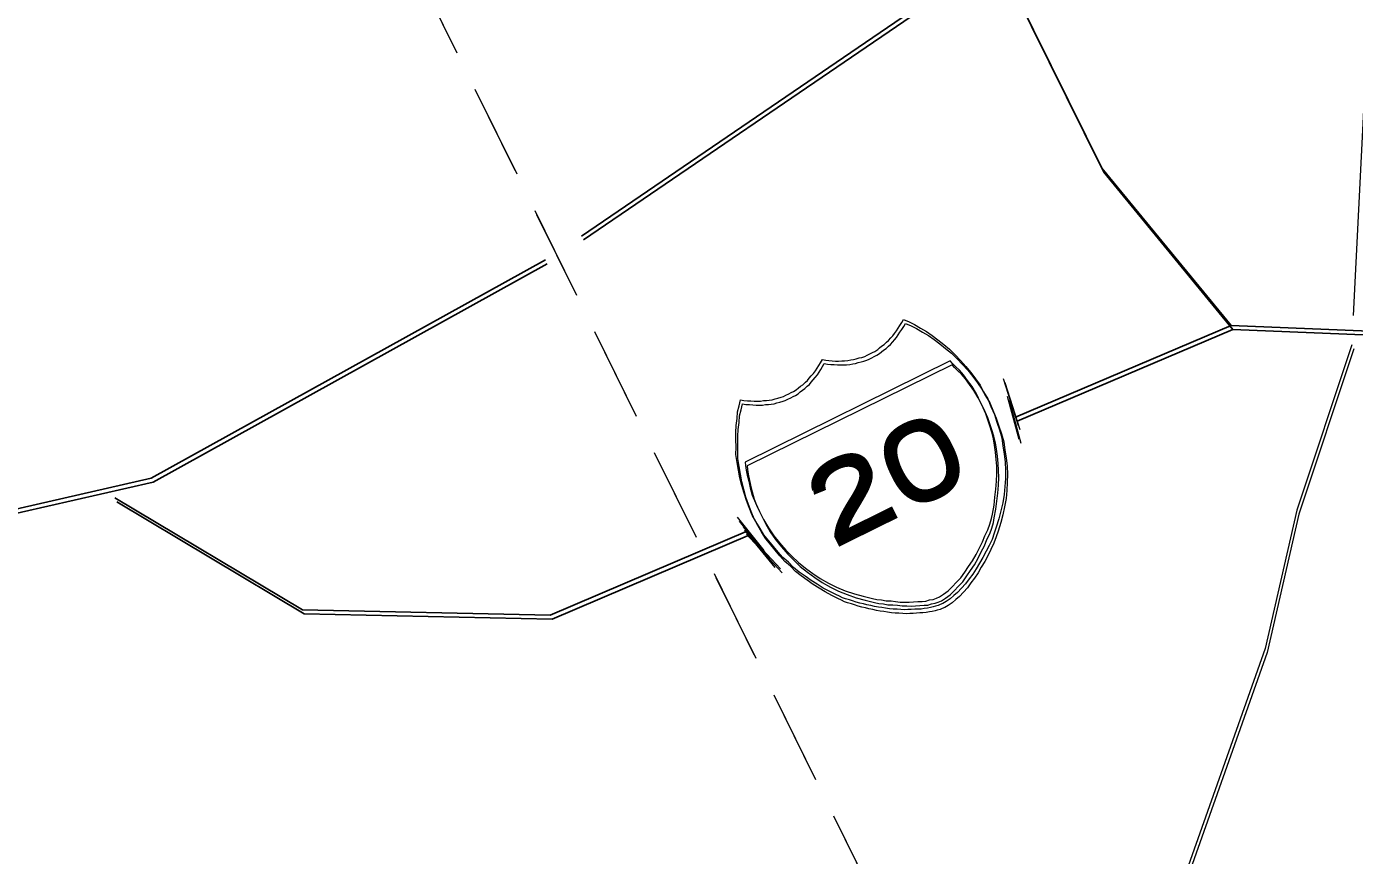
# Model space of a CAD drawing. Extents: x 2356606 to 2371222, y 6973096 to 6982644.
# Drawn here: x 2357158.9 to 2357247.4, y 6973564.3 to 6973619.6 of the extents above; entities that cross this region are included whole.
import ezdxf

# ---------------------------------------------------------------- set-up
doc = ezdxf.new("R2010")
doc.units = 0
doc.header["$LTSCALE"] = 2
doc.linetypes.add('MEDIUM_DASHED', pattern=[4.5, 3, -1.5])
doc.layers.add('62', color=7, linetype='Continuous', lineweight=13)
doc.layers.add('63', color=7, linetype='Continuous', lineweight=13)

msp = doc.modelspace()

# ---------------------------------------------------------------- linework, layer by layer
at = {"layer": '62', "linetype": 'MEDIUM_DASHED'}
msp.add_line((2357160.992, 6973671.606), (2357243.202, 6973505.087), dxfattribs=at)
at = {"layer": '62', "lineweight": 25}
msp.add_line((2357239.274, 6973599.379), (2357224.9, 6973593.262), dxfattribs=at)
at = {"layer": '62'}
for p, q in [((2357224.078, 6973595.841), (2357225.078, 6973592.699)), ((2357224.362, 6973594.655), (2357225.143, 6973591.803)), ((2357206.36, 6973586.595), (2357208.13, 6973584.384)), ((2357206.75, 6973585.96), (2357208.738, 6973583.504)), ((2357206.857, 6973585.739), (2357209.238, 6973583.15))]:
    msp.add_line(p, q, dxfattribs=at)
at = {"layer": '62', "lineweight": 25}
for points in [[(2357397.532, 6973674.071), (2357391.187, 6973669.235), (2357382.618, 6973664.025), (2357370.494, 6973656.862), (2357361.535, 6973652.442), (2357355.506, 6973648.488), (2357352.272, 6973643.756), (2357344.159, 6973637.568), (2357331.099, 6973632.303), (2357319.179, 6973627.424), (2357306.189, 6973621.966), (2357287.579, 6973609.643), (2357267.547, 6973602.895), (2357250.669, 6973598.906), (2357239.274, 6973599.379), (2357230.661, 6973609.861), (2357224.807, 6973621.723), (2357220.224, 6973626.738), (2357220.552, 6973637.313)], [(2357242.801, 6973629.852), (2357237.017, 6973626.569), (2357228.509, 6973625.507), (2357217.835, 6973620.24), (2357195.98, 6973605.338)], [(2357193.577, 6973603.752), (2357167.306, 6973589.206), (2357147.982, 6973584.787), (2357132.687, 6973585.117), (2357117.613, 6973581.188), (2357111.882, 6973576.68)], [(2357207.078, 6973585.696), (2357193.898, 6973580.069), (2357177.383, 6973580.429), (2357164.895, 6973587.89)]]:
    msp.add_lwpolyline(points, dxfattribs=at)
at = {"layer": '62'}
for points in [[(2357212.912, 6973597.008), (2357213.114, 6973597.007), (2357213.335, 6973597.016), (2357213.506, 6973597.026), (2357213.729, 6973597.035), (2357213.93, 6973597.085), (2357214.122, 6973597.102), (2357214.292, 6973597.163), (2357214.492, 6973597.211), (2357214.676, 6973597.25), (2357214.865, 6973597.318), (2357215.028, 6973597.399), (2357215.21, 6973597.491), (2357215.371, 6973597.571), (2357215.533, 6973597.65), (2357215.726, 6973597.77), (2357215.846, 6973597.879), (2357215.987, 6973598), (2357216.16, 6973598.11), (2357216.311, 6973598.26), (2357216.455, 6973598.381), (2357216.595, 6973598.549), (2357216.726, 6973598.689), (2357216.846, 6973598.848), (2357216.971, 6973599.011), (2357217.08, 6973599.192), (2357217.212, 6973599.382), (2357217.344, 6973599.575), (2357217.446, 6973599.775), (2357217.827, 6973599.613), (2357218.189, 6973599.436), (2357218.58, 6973599.203), (2357218.972, 6973598.971), (2357219.353, 6973598.704), (2357219.744, 6973598.422), (2357220.125, 6973598.108), (2357220.505, 6973597.794), (2357220.896, 6973597.409), (2357221.254, 6973597.035), (2357221.598, 6973596.65), (2357221.927, 6973596.237), (2357222.237, 6973595.812), (2357222.546, 6973595.389), (2357222.785, 6973594.955), (2357223.065, 6973594.491), (2357223.263, 6973593.985), (2357223.502, 6973593.452), (2357223.661, 6973592.926), (2357223.838, 6973592.413), (2357223.998, 6973591.89), (2357224.074, 6973591.325), (2357224.152, 6973590.812), (2357224.219, 6973590.268), (2357224.238, 6973589.723), (2357224.234, 6973589.172), (2357224.193, 6973588.649), (2357224.158, 6973588.104), (2357224.056, 6973587.552), (2357223.942, 6973587.02), (2357223.799, 6973586.497), (2357223.624, 6973585.934), (2357223.491, 6973585.542), (2357223.347, 6973585.121), (2357223.144, 6973584.719), (2357222.962, 6973584.329), (2357222.737, 6973583.917), (2357222.502, 6973583.524), (2357222.281, 6973583.163), (2357222.057, 6973582.8), (2357221.813, 6973582.481), (2357221.57, 6973582.161), (2357221.317, 6973581.86), (2357221.055, 6973581.581), (2357220.802, 6973581.38), (2357220.559, 6973581.158), (2357220.296, 6973580.98), (2357220.066, 6973580.841)], [(2357247.334, 6973598.086), (2357243.665, 6973587.068), (2357241.545, 6973577.843), (2357235.54, 6973560.823), (2357231.053, 6973543.631)], [(2357220.066, 6973580.841), (2357219.892, 6973580.779), (2357219.752, 6973580.71), (2357219.57, 6973580.672), (2357219.42, 6973580.623), (2357219.237, 6973580.583), (2357219.056, 6973580.543), (2357218.825, 6973580.505), (2357218.614, 6973580.476), (2357218.413, 6973580.476), (2357218.191, 6973580.466), (2357217.949, 6973580.449), (2357217.728, 6973580.441), (2357217.485, 6973580.421), (2357217.277, 6973580.441), (2357217.014, 6973580.463), (2357216.761, 6973580.465), (2357216.521, 6973580.496), (2357216.248, 6973580.538), (2357216.01, 6973580.57), (2357215.769, 6973580.6), (2357215.516, 6973580.652), (2357215.265, 6973580.705), (2357215.013, 6973580.754), (2357214.782, 6973580.816), (2357214.53, 6973580.87), (2357214.299, 6973580.931), (2357214.058, 6973581.013), (2357213.847, 6973581.083), (2357213.586, 6973581.155), (2357213.375, 6973581.225), (2357213.175, 6973581.329), (2357212.943, 6973581.441), (2357212.54, 6973581.643), (2357212.1, 6973581.879), (2357211.7, 6973582.13), (2357211.298, 6973582.384), (2357210.888, 6973582.659), (2357210.496, 6973582.942), (2357210.125, 6973583.237), (2357209.775, 6973583.59), (2357209.414, 6973583.914), (2357209.083, 6973584.277), (2357208.773, 6973584.653), (2357208.464, 6973585.026), (2357208.144, 6973585.421), (2357207.885, 6973585.842), (2357207.604, 6973586.308), (2357207.367, 6973586.742), (2357207.167, 6973587.248), (2357206.989, 6973587.711), (2357206.819, 6973588.205), (2357206.673, 6973588.709), (2357206.543, 6973589.22), (2357206.444, 6973589.725), (2357206.367, 6973590.238), (2357206.281, 6973590.774), (2357206.283, 6973591.275), (2357206.266, 6973591.77), (2357206.279, 6973592.251), (2357206.299, 6973592.716), (2357206.37, 6973593.177), (2357206.384, 6973593.611), (2357206.486, 6973594.013), (2357206.589, 6973594.416), (2357206.809, 6973594.376), (2357207.043, 6973594.364), (2357207.273, 6973594.353), (2357207.487, 6973594.331), (2357207.706, 6973594.339), (2357207.908, 6973594.338), (2357208.119, 6973594.366), (2357208.321, 6973594.367), (2357208.501, 6973594.405), (2357208.692, 6973594.424), (2357208.885, 6973594.494), (2357209.067, 6973594.533), (2357209.289, 6973594.593), (2357209.439, 6973594.643), (2357209.6, 6973594.722), (2357209.804, 6973594.821), (2357209.964, 6973594.902), (2357210.125, 6973594.979), (2357210.298, 6973595.089), (2357210.439, 6973595.21), (2357210.579, 6973595.328), (2357210.732, 6973595.43), (2357210.905, 6973595.589), (2357211.046, 6973595.71), (2357211.165, 6973595.871), (2357211.298, 6973596.01), (2357211.439, 6973596.181), (2357211.582, 6973596.352), (2357211.693, 6973596.534), (2357211.804, 6973596.715), (2357211.916, 6973596.894), (2357212.037, 6973597.105), (2357212.259, 6973597.063), (2357212.47, 6973597.042), (2357212.701, 6973597.03), (2357212.912, 6973597.008)]]:
    msp.add_lwpolyline(points, dxfattribs=at)
msp.add_lwpolyline([(2357220.563, 6973597.017), (2357206.902, 6973590.275), (2357206.92, 6973590.034), (2357206.969, 6973589.733), (2357207.028, 6973589.409), (2357207.128, 6973589.007), (2357207.225, 6973588.553), (2357207.363, 6973588.071), (2357207.573, 6973587.546), (2357207.85, 6973586.98), (2357208.119, 6973586.435), (2357208.438, 6973585.892), (2357208.796, 6973585.366), (2357209.189, 6973584.882), (2357209.598, 6973584.406), (2357209.998, 6973584), (2357210.439, 6973583.568), (2357210.921, 6973583.201), (2357211.4, 6973582.838), (2357211.893, 6973582.503), (2357212.445, 6973582.197), (2357212.977, 6973581.932), (2357213.567, 6973581.699), (2357214.17, 6973581.495), (2357214.754, 6973581.329), (2357215.378, 6973581.186), (2357215.668, 6973581.103), (2357215.979, 6973581.083), (2357216.282, 6973581.03), (2357216.614, 6973581.017), (2357216.905, 6973580.987), (2357217.227, 6973580.944), (2357217.53, 6973580.945), (2357217.831, 6973580.942), (2357218.122, 6973580.961), (2357218.394, 6973580.97), (2357218.689, 6973580.989), (2357218.927, 6973581.007), (2357219.189, 6973581.086), (2357219.421, 6973581.123), (2357219.634, 6973581.203), (2357219.847, 6973581.286), (2357220.108, 6973581.462), (2357220.421, 6973581.694), (2357220.695, 6973581.953), (2357220.988, 6973582.273), (2357221.27, 6973582.564), (2357221.533, 6973582.945), (2357221.777, 6973583.317), (2357222.043, 6973583.697), (2357222.286, 6973584.12), (2357222.501, 6973584.552), (2357222.703, 6973584.952), (2357222.876, 6973585.365), (2357223.06, 6973585.756), (2357223.203, 6973586.127), (2357223.315, 6973586.51), (2357223.367, 6973586.811), (2357223.48, 6973587.395), (2357223.543, 6973587.927), (2357223.607, 6973588.458), (2357223.64, 6973589.001), (2357223.675, 6973589.496), (2357223.656, 6973589.99), (2357223.627, 6973590.451), (2357223.571, 6973590.925), (2357223.512, 6973591.398), (2357223.453, 6973591.82), (2357223.334, 6973592.265), (2357223.205, 6973592.679), (2357223.077, 6973593.092), (2357222.928, 6973593.494), (2357222.761, 6973593.887), (2357222.581, 6973594.252), (2357222.302, 6973594.816), (2357222.012, 6973595.301), (2357221.713, 6973595.703), (2357221.453, 6973596.077), (2357221.173, 6973596.39), (2357220.933, 6973596.623), (2357220.722, 6973596.847)], close=True, dxfattribs=at)
at = {"layer": '63', "linetype": 'MEDIUM_DASHED'}
msp.add_line((2357160.862, 6973671.869), (2357243.072, 6973505.35), dxfattribs=at)
at = {"layer": '63'}
for p, q in [((2357248.499, 6973624.612), (2357247.274, 6973600.295)), ((2357223.948, 6973596.104), (2357224.948, 6973592.962)), ((2357224.232, 6973594.918), (2357225.013, 6973592.066)), ((2357206.23, 6973586.858), (2357208, 6973584.647)), ((2357206.62, 6973586.223), (2357208.608, 6973583.767)), ((2357206.727, 6973586.002), (2357209.108, 6973583.413))]:
    msp.add_line(p, q, dxfattribs=at)
at = {"layer": '63', "lineweight": 25}
msp.add_line((2357239.144, 6973599.642), (2357224.77, 6973593.525), dxfattribs=at)
for points in [[(2357397.402, 6973674.334), (2357391.057, 6973669.498), (2357382.488, 6973664.288), (2357370.364, 6973657.125), (2357361.405, 6973652.705), (2357355.376, 6973648.751), (2357352.142, 6973644.019), (2357344.029, 6973637.831), (2357330.969, 6973632.566), (2357319.049, 6973627.687), (2357306.059, 6973622.229), (2357287.449, 6973609.906), (2357267.417, 6973603.158), (2357250.539, 6973599.169), (2357239.144, 6973599.642), (2357230.531, 6973610.124), (2357224.677, 6973621.986), (2357220.094, 6973627.001), (2357220.422, 6973637.576)], [(2357242.671, 6973630.115), (2357236.887, 6973626.832), (2357228.379, 6973625.77), (2357217.705, 6973620.503), (2357195.85, 6973605.601)], [(2357193.447, 6973604.015), (2357167.176, 6973589.469), (2357147.852, 6973585.05), (2357132.557, 6973585.38), (2357117.483, 6973581.451), (2357111.752, 6973576.943)], [(2357206.948, 6973585.959), (2357193.768, 6973580.332), (2357177.253, 6973580.692), (2357164.765, 6973588.153)]]:
    msp.add_lwpolyline(points, dxfattribs=at)
at = {"layer": '63'}
for points in [[(2357212.782, 6973597.271), (2357212.984, 6973597.27), (2357213.205, 6973597.279), (2357213.376, 6973597.289), (2357213.599, 6973597.298), (2357213.8, 6973597.348), (2357213.992, 6973597.365), (2357214.162, 6973597.426), (2357214.362, 6973597.474), (2357214.546, 6973597.513), (2357214.735, 6973597.581), (2357214.898, 6973597.662), (2357215.08, 6973597.754), (2357215.241, 6973597.834), (2357215.403, 6973597.913), (2357215.596, 6973598.033), (2357215.716, 6973598.142), (2357215.857, 6973598.263), (2357216.03, 6973598.373), (2357216.181, 6973598.523), (2357216.325, 6973598.644), (2357216.465, 6973598.812), (2357216.596, 6973598.952), (2357216.716, 6973599.111), (2357216.841, 6973599.274), (2357216.95, 6973599.455), (2357217.082, 6973599.645), (2357217.214, 6973599.838), (2357217.316, 6973600.038), (2357217.697, 6973599.876), (2357218.059, 6973599.699), (2357218.45, 6973599.466), (2357218.842, 6973599.234), (2357219.223, 6973598.967), (2357219.614, 6973598.685), (2357219.995, 6973598.371), (2357220.375, 6973598.057), (2357220.766, 6973597.672), (2357221.124, 6973597.298), (2357221.468, 6973596.913), (2357221.797, 6973596.5), (2357222.107, 6973596.075), (2357222.416, 6973595.652), (2357222.655, 6973595.218), (2357222.935, 6973594.754), (2357223.133, 6973594.248), (2357223.372, 6973593.715), (2357223.531, 6973593.189), (2357223.708, 6973592.676), (2357223.868, 6973592.153), (2357223.944, 6973591.588), (2357224.022, 6973591.075), (2357224.089, 6973590.531), (2357224.108, 6973589.986), (2357224.104, 6973589.435), (2357224.063, 6973588.912), (2357224.028, 6973588.367), (2357223.926, 6973587.815), (2357223.812, 6973587.283), (2357223.669, 6973586.76), (2357223.494, 6973586.197), (2357223.361, 6973585.805), (2357223.217, 6973585.384), (2357223.014, 6973584.982), (2357222.832, 6973584.592), (2357222.607, 6973584.18), (2357222.372, 6973583.787), (2357222.151, 6973583.426), (2357221.927, 6973583.063), (2357221.683, 6973582.744), (2357221.44, 6973582.424), (2357221.187, 6973582.123), (2357220.925, 6973581.844), (2357220.672, 6973581.643), (2357220.429, 6973581.421), (2357220.166, 6973581.243), (2357219.936, 6973581.104)], [(2357247.204, 6973598.349), (2357243.535, 6973587.331), (2357241.415, 6973578.106), (2357235.41, 6973561.086), (2357230.923, 6973543.894)], [(2357219.936, 6973581.104), (2357219.762, 6973581.042), (2357219.622, 6973580.973), (2357219.44, 6973580.935), (2357219.29, 6973580.886), (2357219.107, 6973580.846), (2357218.926, 6973580.806), (2357218.695, 6973580.768), (2357218.484, 6973580.739), (2357218.283, 6973580.739), (2357218.061, 6973580.729), (2357217.819, 6973580.712), (2357217.598, 6973580.704), (2357217.355, 6973580.684), (2357217.147, 6973580.704), (2357216.884, 6973580.726), (2357216.631, 6973580.728), (2357216.391, 6973580.759), (2357216.118, 6973580.801), (2357215.88, 6973580.833), (2357215.639, 6973580.863), (2357215.386, 6973580.915), (2357215.135, 6973580.968), (2357214.883, 6973581.017), (2357214.652, 6973581.079), (2357214.4, 6973581.133), (2357214.169, 6973581.194), (2357213.928, 6973581.276), (2357213.717, 6973581.346), (2357213.456, 6973581.418), (2357213.245, 6973581.488), (2357213.045, 6973581.592), (2357212.813, 6973581.704), (2357212.41, 6973581.906), (2357211.97, 6973582.142), (2357211.57, 6973582.393), (2357211.168, 6973582.647), (2357210.758, 6973582.922), (2357210.366, 6973583.205), (2357209.995, 6973583.5), (2357209.645, 6973583.853), (2357209.284, 6973584.177), (2357208.953, 6973584.54), (2357208.643, 6973584.916), (2357208.334, 6973585.289), (2357208.014, 6973585.684), (2357207.755, 6973586.105), (2357207.474, 6973586.571), (2357207.237, 6973587.005), (2357207.037, 6973587.511), (2357206.859, 6973587.974), (2357206.689, 6973588.468), (2357206.543, 6973588.972), (2357206.413, 6973589.483), (2357206.314, 6973589.988), (2357206.237, 6973590.501), (2357206.151, 6973591.037), (2357206.153, 6973591.538), (2357206.136, 6973592.033), (2357206.149, 6973592.514), (2357206.169, 6973592.979), (2357206.24, 6973593.44), (2357206.254, 6973593.874), (2357206.356, 6973594.276), (2357206.459, 6973594.679), (2357206.679, 6973594.639), (2357206.913, 6973594.627), (2357207.143, 6973594.616), (2357207.357, 6973594.594), (2357207.576, 6973594.602), (2357207.778, 6973594.601), (2357207.989, 6973594.629), (2357208.191, 6973594.63), (2357208.371, 6973594.668), (2357208.562, 6973594.687), (2357208.755, 6973594.757), (2357208.937, 6973594.796), (2357209.159, 6973594.856), (2357209.309, 6973594.906), (2357209.47, 6973594.985), (2357209.674, 6973595.084), (2357209.834, 6973595.165), (2357209.995, 6973595.242), (2357210.168, 6973595.352), (2357210.309, 6973595.473), (2357210.449, 6973595.591), (2357210.602, 6973595.693), (2357210.775, 6973595.852), (2357210.916, 6973595.973), (2357211.035, 6973596.134), (2357211.168, 6973596.273), (2357211.309, 6973596.444), (2357211.452, 6973596.615), (2357211.563, 6973596.797), (2357211.674, 6973596.978), (2357211.786, 6973597.157), (2357211.907, 6973597.368), (2357212.129, 6973597.326), (2357212.34, 6973597.305), (2357212.571, 6973597.293), (2357212.782, 6973597.271)]]:
    msp.add_lwpolyline(points, dxfattribs=at)
msp.add_lwpolyline([(2357220.433, 6973597.28), (2357206.772, 6973590.538), (2357206.79, 6973590.297), (2357206.839, 6973589.996), (2357206.898, 6973589.672), (2357206.998, 6973589.27), (2357207.095, 6973588.816), (2357207.233, 6973588.334), (2357207.443, 6973587.809), (2357207.72, 6973587.243), (2357207.989, 6973586.698), (2357208.308, 6973586.155), (2357208.666, 6973585.629), (2357209.059, 6973585.145), (2357209.468, 6973584.669), (2357209.868, 6973584.263), (2357210.309, 6973583.831), (2357210.791, 6973583.464), (2357211.27, 6973583.101), (2357211.763, 6973582.766), (2357212.315, 6973582.46), (2357212.847, 6973582.195), (2357213.437, 6973581.962), (2357214.04, 6973581.758), (2357214.624, 6973581.592), (2357215.248, 6973581.449), (2357215.538, 6973581.366), (2357215.849, 6973581.346), (2357216.152, 6973581.293), (2357216.484, 6973581.28), (2357216.775, 6973581.25), (2357217.097, 6973581.207), (2357217.4, 6973581.208), (2357217.701, 6973581.205), (2357217.992, 6973581.224), (2357218.264, 6973581.233), (2357218.559, 6973581.252), (2357218.797, 6973581.27), (2357219.059, 6973581.349), (2357219.291, 6973581.386), (2357219.504, 6973581.466), (2357219.717, 6973581.549), (2357219.978, 6973581.725), (2357220.291, 6973581.957), (2357220.565, 6973582.216), (2357220.858, 6973582.536), (2357221.14, 6973582.827), (2357221.403, 6973583.208), (2357221.647, 6973583.58), (2357221.913, 6973583.96), (2357222.156, 6973584.383), (2357222.371, 6973584.815), (2357222.573, 6973585.215), (2357222.746, 6973585.628), (2357222.93, 6973586.019), (2357223.073, 6973586.39), (2357223.185, 6973586.773), (2357223.237, 6973587.074), (2357223.35, 6973587.658), (2357223.413, 6973588.19), (2357223.477, 6973588.721), (2357223.51, 6973589.264), (2357223.545, 6973589.759), (2357223.526, 6973590.253), (2357223.497, 6973590.714), (2357223.441, 6973591.188), (2357223.382, 6973591.661), (2357223.323, 6973592.083), (2357223.204, 6973592.528), (2357223.075, 6973592.942), (2357222.947, 6973593.355), (2357222.798, 6973593.757), (2357222.631, 6973594.15), (2357222.451, 6973594.515), (2357222.172, 6973595.079), (2357221.882, 6973595.564), (2357221.583, 6973595.966), (2357221.323, 6973596.34), (2357221.043, 6973596.653), (2357220.803, 6973596.886), (2357220.592, 6973597.11)], close=True, dxfattribs=at)

# ---------------------------------------------------------------- texts
at = {"layer": '62', "width": 1.4}
msp.add_text('20', height=5.099, rotation=26.268, dxfattribs=at).set_placement((2357212.597, 6973584.683))
at = {"layer": '63', "width": 1.4}
msp.add_text('20', height=5.099, rotation=26.268, dxfattribs=at).set_placement((2357212.467, 6973584.947))

doc.saveas('drawing.dxf')
